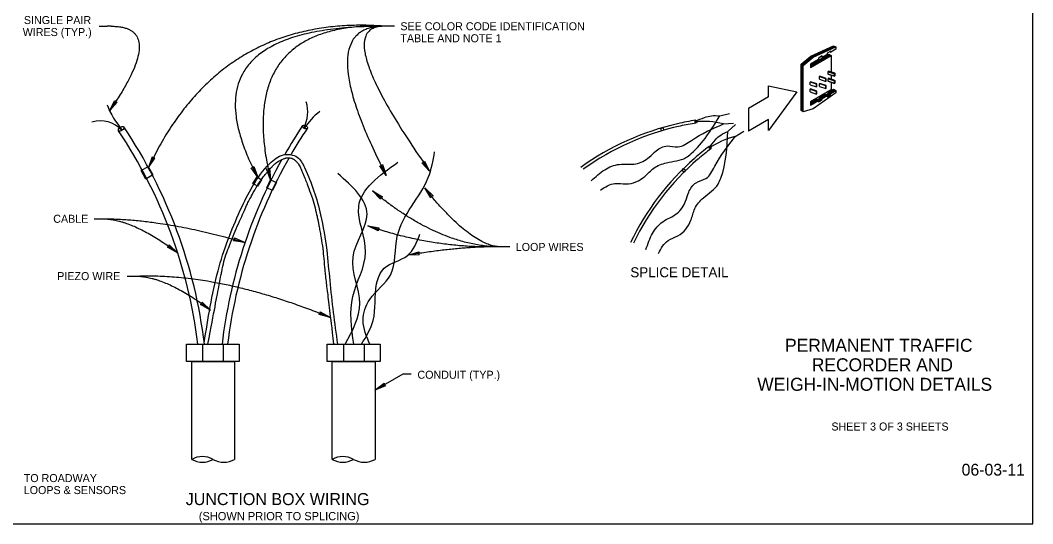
# Model space of a CAD drawing. Extents: x 99862 to 103151, y 100000 to 108076.
# Drawn here: x 101127 to 103151, y 106000 to 107006 of the extents above; entities that cross this region are included whole.
import ezdxf

# ---------------------------------------------------------------- set-up
doc = ezdxf.new("R2010")
doc.units = 0
for name, color, linetype in [('Level 1', 7, 'Continuous'), ('Level 15', 7, 'Continuous'), ('Level 2', 7, 'Continuous'), ('Level 20', 7, 'Continuous'), ('Level 21', 7, 'Continuous'), ('Level 30', 7, 'Continuous'), ('Level 34', 7, 'Continuous'), ('Level 62', 7, 'Continuous')]:
    doc.layers.add(name, color=color, linetype=linetype)

msp = doc.modelspace()

# ---------------------------------------------------------------- linework, layer by layer
at = {"layer": 'Level 1'}
msp.add_lwpolyline([(99862, 105999.5), (103151, 105999.5), (103151, 108075.5), (99862, 108075.5)], close=True, dxfattribs=at)
msp.add_lwpolyline([(99862, 105999.5), (103151, 105999.5), (103151, 108075.5), (99862, 108075.5)], close=True, dxfattribs=at)
at = {"layer": 'Level 15'}
for p, q in [((101285.3, 106994.1), (101301.3, 106994.1)), ((101309.3, 106994.1), (101301.3, 106994.1)), ((101875.2, 106994.1), (101855.5, 106994.1)), ((101275.4, 106609.2), (101291.4, 106609.2)), ((102082.1, 106552.9), (102066.1, 106552.9)), ((102105.8, 106552.9), (102089.8, 106552.9)), ((102105.8, 106552.9), (102103.9, 106552.9)), ((101341.4, 106494.6), (101357.4, 106494.6)), ((101836.3, 106266.4), (101892.5, 106298.9)), ((101892.5, 106298.9), (101908.5, 106298.9))]:
    msp.add_line(p, q, dxfattribs=at)
for points in [[(101306, 106825.2), (101316.4, 106845.7), (101318.2, 106843.1), (101321.3, 106842.3)], [(101383.5, 106711.6), (101396.5, 106730.6), (101393.4, 106731), (101391.2, 106733.3)], [(101945.7, 106704.2), (101930.2, 106721.2), (101933.2, 106722), (101935.1, 106724.6)], [(101602.1, 106692.1), (101589.2, 106711.2), (101592.3, 106711.6), (101594.5, 106713.9)], [(101627.7, 106687.4), (101619.9, 106709), (101623, 106708.6), (101625.7, 106710.3)], [(101858.8, 106695.8), (101845.9, 106714.9), (101849.1, 106715.2), (101851.3, 106717.5)], [(101831.5, 106665.1), (101851.2, 106653.2), (101848.5, 106651.5), (101847.4, 106648.5)], [(101935.9, 106670.9), (101952.7, 106655.1), (101949.7, 106654), (101948.1, 106651.3)], [(101822, 106595.2), (101844.6, 106590.9), (101842.7, 106588.4), (101842.7, 106585.2)], [(101576.7, 106561.7), (101553.9, 106565.1), (101555.7, 106567.7), (101555.5, 106570.8)], [(101442, 106541.3), (101421.7, 106552.2), (101424.3, 106554), (101425.2, 106557.1)], [(101901.9, 106536.5), (101924, 106543.1), (101923.4, 106540), (101924.9, 106537.2)], [(101508, 106426.7), (101487.7, 106437.6), (101490.3, 106439.4), (101491.2, 106442.5)], [(101747.3, 106411.9), (101725, 106417.8), (101727.1, 106420.2), (101727.2, 106423.3)], [(101836.3, 106266.4), (101854.5, 106280.4), (101855.1, 106277.3), (101857.5, 106275.2)]]:
    msp.add_lwpolyline(points, close=True, dxfattribs=at)
for points in [[(101309.3, 106994.1), (101423, 106994.1), (101306, 106825.2)], [(101859.1, 106994.1), (101529, 107019.6), (101384.4, 106712.9)], [(101855.5, 106994.1), (101441.5, 106994.1), (101602.1, 106692.1)], [(101871.5, 106994.1), (101550.7, 107009.3), (101627.7, 106687.4)], [(101855.5, 106994.1), (101705.4, 106994.1), (101858.8, 106695.8)], [(101855.5, 106994.1), (101741.8, 106994.1), (101945.6, 106704.3)], [(102089.8, 106552.9), (101966.3, 106552.9), (101831.5, 106665.1)], [(102089.8, 106552.9), (102029.4, 106552.9), (101935.9, 106670.9)], [(101291.4, 106609.2), (101414.9, 106609.2), (101576.7, 106561.7)], [(101291.4, 106609.2), (101351.8, 106609.2), (101442, 106541.3)], [(102066.1, 106552.9), (101942.6, 106552.9), (101822, 106595.2)], [(102066.1, 106552.9), (102005.8, 106552.9), (101901.9, 106536.5)], [(101357.4, 106494.6), (101527, 106502), (101747.3, 106411.9)], [(101357.4, 106494.6), (101417.8, 106494.6), (101508, 106426.7)]]:
    msp.add_open_spline(points, degree=2, dxfattribs=at)
at = {"layer": 'Level 2'}
for p, q in [((102747.4, 106944.6), (102739.9, 106940.3)), ((102745.3, 106943.4), (102747.4, 106942.2)), ((102757.6, 106948), (102747.4, 106942.2)), ((102747.4, 106942.2), (102747.4, 106944.6)), ((102753, 106955.3), (102757.6, 106952.7)), ((102757.6, 106952.7), (102757.6, 106948)), ((102706.6, 106911.6), (102748.2, 106935.7)), ((102707.6, 106934.6), (102712.1, 106932)), ((102730.2, 106934.7), (102722.7, 106930.3)), ((102722.7, 106930.3), (102722.7, 106927.9)), ((102730.2, 106932.2), (102728, 106933.4)), ((102739.9, 106937.8), (102730.2, 106932.2)), ((102730.2, 106932.2), (102730.2, 106934.7)), ((102739.9, 106940.3), (102739.9, 106937.8)), ((102743.7, 106938.3), (102748.2, 106935.7)), ((102748.2, 106935.7), (102748.2, 106902.7)), ((102692.5, 106915.5), (102688, 106918.1)), ((102742.8, 106904.3), (102742, 106903.5)), ((102742, 106898.3), (102742, 106903.5)), ((102742.8, 106903.3), (102742, 106903.5)), ((102755.4, 106900.1), (102742.8, 106904.3)), ((102754.6, 106899.3), (102742.8, 106903.3)), ((102743, 106904.2), (102755.4, 106900.1)), ((102743, 106903.2), (102754.6, 106899.3)), ((102706.7, 106883.1), (102705.9, 106882.3)), ((102705.9, 106877.1), (102705.9, 106882.3)), ((102706.7, 106882.1), (102705.9, 106882.3)), ((102719.3, 106878.9), (102706.7, 106883.1)), ((102719.3, 106878.9), (102706.7, 106883.1)), ((102718.5, 106878.1), (102706.7, 106882.1)), ((102718.5, 106878.1), (102706.7, 106882.1)), ((102725.7, 106894.2), (102724.9, 106893.4)), ((102724.9, 106888.2), (102724.9, 106893.4)), ((102725.7, 106893.1), (102724.9, 106893.4)), ((102724.9, 106888.2), (102737.5, 106883.9)), ((102738.3, 106889.9), (102725.7, 106894.2)), ((102737.5, 106889.1), (102725.7, 106893.1)), ((102738.3, 106889.9), (102737.5, 106889.1)), ((102737.5, 106883.9), (102737.5, 106889.1)), ((102737.5, 106883.9), (102738.3, 106884.7)), ((102738.3, 106884.7), (102738.3, 106889.9)), ((102742, 106898.3), (102754.6, 106894.1)), ((102742.8, 106890.1), (102742, 106889.3)), ((102742, 106884), (102742, 106889.3)), ((102742.8, 106889), (102742, 106889.3)), ((102742, 106884), (102754.6, 106879.8)), ((102754.6, 106894.1), (102742.2, 106898.2)), ((102754.6, 106879.8), (102742.2, 106884)), ((102755.4, 106885.8), (102742.8, 106890.1)), ((102754.6, 106885), (102742.8, 106889)), ((102743, 106890), (102755.4, 106885.8)), ((102743, 106888.9), (102754.6, 106885)), ((102748.2, 106881.9), (102748.2, 106867.1)), ((102755.4, 106900.1), (102754.6, 106899.3)), ((102755.4, 106900.1), (102754.6, 106899.3)), ((102754.6, 106899.3), (102754.6, 106894.1)), ((102754.6, 106894.1), (102754.6, 106899.3)), ((102754.6, 106894.1), (102755.4, 106894.9)), ((102754.6, 106894.1), (102755.4, 106894.9)), ((102755.4, 106885.8), (102754.6, 106885)), ((102755.4, 106885.8), (102754.6, 106885)), ((102754.6, 106885), (102754.6, 106879.8)), ((102754.6, 106879.8), (102754.6, 106885)), ((102755.4, 106900.1), (102755.4, 106894.9)), ((102755.4, 106894.9), (102755.4, 106900.1)), ((102755.4, 106885.8), (102755.4, 106880.6)), ((102755.4, 106880.6), (102755.4, 106885.8)), ((102623, 106852.9), (102623, 106875)), ((102692.5, 106865.3), (102688, 106867.9)), ((102692.5, 106823.3), (102692.5, 106865.3)), ((102705.9, 106877.1), (102718.5, 106872.9)), ((102705.9, 106877.1), (102718.5, 106872.9)), ((102706.7, 106868.9), (102705.9, 106868.1)), ((102705.9, 106862.8), (102705.9, 106868.1)), ((102706.7, 106867.8), (102705.9, 106868.1)), ((102705.9, 106862.8), (102718.5, 106858.6)), ((102705.9, 106862.8), (102718.5, 106858.6)), ((102748.2, 106867.1), (102706.6, 106843)), ((102719.3, 106864.6), (102706.7, 106868.9)), ((102719.3, 106864.6), (102706.7, 106868.9)), ((102718.5, 106863.8), (102706.7, 106867.8)), ((102718.5, 106863.8), (102706.7, 106867.8)), ((102719.3, 106878.9), (102718.5, 106878.1)), ((102719.3, 106878.9), (102718.5, 106878.1)), ((102718.5, 106872.9), (102718.5, 106878.1)), ((102718.5, 106872.9), (102718.5, 106878.1)), ((102718.5, 106872.9), (102719.3, 106873.7)), ((102718.5, 106872.9), (102719.3, 106873.7)), ((102719.3, 106864.6), (102718.5, 106863.8)), ((102719.3, 106864.6), (102718.5, 106863.8)), ((102718.5, 106858.6), (102718.5, 106863.8)), ((102718.5, 106858.6), (102718.5, 106863.8)), ((102719.3, 106873.7), (102719.3, 106878.9)), ((102719.3, 106873.7), (102719.3, 106878.9)), ((102719.3, 106859.4), (102719.3, 106864.6)), ((102719.3, 106859.4), (102719.3, 106864.6)), ((102725.7, 106879.9), (102724.9, 106879.1)), ((102724.9, 106873.9), (102724.9, 106879.1)), ((102725.7, 106878.8), (102724.9, 106879.1)), ((102724.9, 106873.9), (102737.5, 106869.7)), ((102724.9, 106873.9), (102737.5, 106869.7)), ((102738.3, 106875.7), (102725.7, 106879.9)), ((102738.3, 106875.7), (102725.7, 106879.9)), ((102737.5, 106874.9), (102725.7, 106878.8)), ((102737.5, 106874.9), (102725.7, 106878.8)), ((102738.3, 106875.7), (102737.5, 106874.9)), ((102738.3, 106875.7), (102737.5, 106874.9)), ((102737.5, 106869.7), (102737.5, 106874.9)), ((102737.5, 106869.7), (102737.5, 106874.9)), ((102737.5, 106869.7), (102738.3, 106870.4)), ((102737.5, 106869.7), (102738.3, 106870.4)), ((102738.3, 106870.4), (102738.3, 106875.7)), ((102738.3, 106870.4), (102738.3, 106875.7)), ((102742.9, 106862.6), (102753, 106868.4)), ((102742.9, 106860.1), (102742.9, 106862.6)), ((102742.9, 106862.6), (102747.4, 106860)), ((102745.2, 106861.3), (102755.3, 106867.1)), ((102747.4, 106860), (102757.6, 106865.8)), ((102753, 106868.4), (102757.6, 106865.8)), ((102754.6, 106879.8), (102755.4, 106880.6)), ((102754.6, 106879.8), (102755.4, 106880.6)), ((102757.6, 106865.8), (102757.6, 106861.1)), ((102623, 106852.9), (102583, 106829.9)), ((102757.6, 106861.1), (102712.1, 106829.3)), ((102722.7, 106845.7), (102718.1, 106848.3)), ((102718.5, 106858.6), (102719.3, 106859.4)), ((102718.5, 106858.6), (102719.3, 106859.4)), ((102720.3, 106847), (102725.6, 106850.1)), ((102722.5, 106845.7), (102727.9, 106848.8)), ((102722.7, 106843.2), (102730.2, 106847.5)), ((102722.7, 106845.7), (102722.7, 106843.2)), ((102725.6, 106852.6), (102735.4, 106858.2)), ((102725.6, 106850.1), (102725.6, 106852.6)), ((102725.6, 106852.6), (102730.2, 106850)), ((102730.2, 106847.5), (102725.6, 106850.1)), ((102727.9, 106851.3), (102737.7, 106856.9)), ((102727.9, 106848.8), (102727.9, 106851.3)), ((102730.2, 106850), (102739.9, 106855.6)), ((102730.2, 106847.5), (102730.2, 106850)), ((102735.4, 106858.2), (102739.9, 106855.6)), ((102737.5, 106857), (102742.9, 106860.1)), ((102739.8, 106855.7), (102745.2, 106858.8)), ((102739.9, 106853.2), (102747.4, 106857.5)), ((102739.9, 106855.6), (102739.9, 106853.2)), ((102747.4, 106857.5), (102742.9, 106860.1)), ((102745.2, 106858.8), (102745.2, 106861.3)), ((102747.4, 106857.5), (102747.4, 106860)), ((102583, 106829.9), (102583, 106784.7)), ((102692.5, 106823.3), (102688, 106825.9)), ((102712.1, 106829.3), (102692.5, 106823.3)), ((102623, 106807.8), (102583, 106784.7)), ((102623, 106785.7), (102623, 106807.8))]:
    msp.add_line(p, q, dxfattribs=at)
for points in [[(102688, 106867.9), (102688, 106918.1), (102707.6, 106934.6), (102753, 106955.3)], [(102690.3, 106866.6), (102690.3, 106916.8), (102709.8, 106933.3), (102755.3, 106954)], [(102692.5, 106865.3), (102692.5, 106915.5), (102712.1, 106932), (102757.6, 106952.7)], [(102706.6, 106916.9), (102743.7, 106938.3)], [(102706.6, 106914.2), (102746, 106937)], [(102722.7, 106927.9), (102706.6, 106918.6), (102706.6, 106911.6)], [(102748.2, 106896.4), (102748.2, 106888.3)], [(102623, 106875), (102679.5, 106863), (102623, 106785.7)], [(102688, 106825.9), (102688, 106867.9)], [(102690.3, 106824.6), (102690.3, 106866.6)], [(102706.6, 106841.6), (102718.1, 106848.3)], [(102706.6, 106839), (102720.4, 106847)], [(102706.6, 106843), (102706.6, 106836.4), (102722.7, 106845.7)]]:
    msp.add_lwpolyline(points, dxfattribs=at)
at = {"layer": 'Level 21'}
for p, q in [((102525.4, 106815), (102545.2, 106819.7)), ((102525.4, 106814.8), (102545.2, 106819.6)), ((102532.7, 106799), (102553.1, 106800.2)), ((102532.7, 106798.9), (102553.1, 106800.1)), ((102541.9, 106784), (102557.1, 106797.7)), ((102541.9, 106784), (102557.1, 106797.7)), ((102556, 106773.6), (102573.3, 106784.3)), ((102556, 106773.6), (102573.3, 106784.3))]:
    msp.add_line(p, q, dxfattribs=at)
for points in [[(102411.9, 106791.6), (102413.8, 106786.6), (102409.3, 106784.8), (102407.4, 106789.9)], [(102453.2, 106709.6), (102457.3, 106706.1), (102454.1, 106702.4), (102450, 106705.9)]]:
    msp.add_lwpolyline(points, close=True, dxfattribs=at)
for centre, radius, start, end in [((102561.9, 106267.2), 545.6, 98.8527, 102.8221), ((102493.8, 106648.4), 155.5, 75.503, 96.3909), ((102559.4, 106279.9), 532.6, 102.8706, 125.7956), ((102559.4, 106279.9), 526.9, 102.4053, 125.6163), ((102559.4, 106279.9), 526.9, 98.872, 102.3942), ((102593.4, 106622.7), 155.5, 103.9459, 124.8339), ((102834.8, 106319.9), 545.6, 127.2956, 131.265), ((102825.1, 106326.6), 528.4, 126.8925, 130.4825), ((102826.6, 106330), 532.6, 131.3135, 154.2385), ((102826.6, 106330), 526.9, 130.8483, 154.0592)]:
    msp.add_arc(centre, radius, start, end, dxfattribs=at)
for centre, major_axis in [((102478.1, 106803.4), (-0.82, 2.91)), ((102505.8, 106751.5), (-2.1, 2.17))]:
    msp.add_ellipse(centre, major_axis=major_axis, ratio=0.557118, dxfattribs=at)
for points in [[(102286.9, 106666.5), (102316.1, 106679.8), (102338, 106678.8), (102375.7, 106694), (102393.6, 106710.4), (102419.1, 106721.2), (102457.9, 106731.5), (102468.4, 106739.4), (102525.4, 106814.8)], [(102476.6, 106804), (102495, 106811.7), (102509.2, 106815.2), (102525.4, 106814.8)], [(102268.7, 106685.1), (102295.7, 106707.2), (102324.7, 106718), (102357.6, 106719), (102384.6, 106732.5), (102398.4, 106745.2), (102420.5, 106754.8), (102441.9, 106753), (102468.8, 106766), (102532.7, 106798.9)], [(102402.9, 106540), (102422.2, 106565.6), (102442, 106575.3), (102467.8, 106606.5), (102475.7, 106629.5), (102493.1, 106651.2), (102522.3, 106678.7), (102527.7, 106690.6), (102541.9, 106784)], [(102504.2, 106751.3), (102516.7, 106766.8), (102527.5, 106776.7), (102541.9, 106784)], [(102377.9, 106547.8), (102391.2, 106580), (102411.5, 106603.3), (102440, 106619.9), (102457.3, 106644.7), (102463.4, 106662.3), (102478.3, 106681.3), (102497.9, 106689.9), (102515.5, 106714.2), (102556, 106773.6)]]:
    msp.add_spline(points, degree=3, dxfattribs=at)
at = {"layer": 'Level 30'}
for points in [[(101369, 106705.7), (101383.2, 106713.9), (101392.6, 106696.8), (101378.5, 106688.6)], [(101600.7, 106693), (101609.8, 106687.2), (101601.5, 106674.2), (101592.4, 106680)], [(101627.7, 106687.4), (101639.5, 106681.7), (101631.8, 106665.6), (101620, 106671.3)]]:
    msp.add_lwpolyline(points, close=True, dxfattribs=at)
for centre, radius, start, end in [((100512, 106240.6), 977.5, 6.9349, 33.8459), ((100511.4, 106240.5), 991.2, 6.8428, 33.8815), ((102522.6, 106241.3), 998.7, 146.2911, 150.187), ((102522.6, 106241.3), 987.9, 146.2898, 149.8076), ((102522.6, 106241.3), 998.7, 150.8675, 173.2505), ((102528.1, 106240.2), 993.2, 150.3711, 173.15)]:
    msp.add_arc(centre, radius, start, end, dxfattribs=at)
for centre, major_axis, ratio in [((101329.1, 106789), (-5.11, -3.88), 0.557118), ((101696.4, 106792.6), (-4.86, 2.46), 0.579152)]:
    msp.add_ellipse(centre, major_axis=major_axis, ratio=ratio, dxfattribs=at)
at = {"layer": 'Level 34'}
for p, q in [((102525.4, 106815), (102525.4, 106814.8)), ((101491.9, 106358.6), (101491.9, 106325.3)), ((101533.1, 106358), (101533.1, 106324.7)), ((101773.3, 106358.6), (101773.3, 106325.3)), ((101814.5, 106358), (101814.5, 106324.7))]:
    msp.add_line(p, q, dxfattribs=at)
for points in [[(101459.8, 106358.6), (101565.2, 106358.6), (101565.2, 106324.1), (101459.8, 106324.1)], [(101741.2, 106358.6), (101846.6, 106358.6), (101846.6, 106324.1), (101741.2, 106324.1)]]:
    msp.add_lwpolyline(points, close=True, dxfattribs=at)
for points in [[(101470.3, 106128.2), (101470.3, 106323.9), (101555.9, 106323.9), (101555.9, 106128.2)], [(101751, 106128.2), (101751, 106323.9), (101836.6, 106323.9), (101836.6, 106128.2)]]:
    msp.add_lwpolyline(points, dxfattribs=at)
for centre, radius, start, end in [((101634.1, 106823.1), 68, 331.3678, 16.8859), ((101450.6, 106893.6), 160, 200.6632, 222.0025), ((101802.5, 106723.9), 125.6, 127.5808, 148.4638), ((101287.8, 106746.8), 58.1, 42.2832, 107.0105), ((101491.6, 106091.6), 42.3, 60, 120.1137), ((101772.3, 106091.6), 42.3, 60, 120.1137), ((101491.6, 106164.8), 42.3, 239.9024, 300), ((101534.3, 106165.6), 43.2, 240, 300), ((101772.3, 106164.8), 42.3, 239.9024, 300), ((101815, 106165.6), 43.2, 240, 300)]:
    msp.add_arc(centre, radius, start, end, dxfattribs=at)
for points in [[(101826, 106358.6), (101812.7, 106406), (101826, 106447.9), (101867.2, 106496.8), (101881, 106574.6), (101942.8, 106691.5), (101955.6, 106743.1)], [(101495.2, 106361.2), (101522.9, 106505.4), (101567.2, 106626.1), (101592.4, 106675.1), (101626, 106719.4), (101653.5, 106736.9), (101681, 106732.4), (101695.6, 106711.7), (101727.7, 106617), (101739.9, 106546.7), (101746, 106485.5), (101761.4, 106358.6)], [(101794, 106358.6), (101792.1, 106454.1), (101817.7, 106542.2), (101804, 106633.6), (101882.3, 106722.3)], [(101777.1, 106358.8), (101806, 106439.9), (101792.8, 106533.2), (101820.5, 106618.5), (101762.3, 106699.8)], [(101809.5, 106358.6), (101832.8, 106406), (101839.7, 106479.2), (101854.8, 106510.2), (101901.2, 106535.6), (101926.1, 106578.4)]]:
    msp.add_spline(points, degree=3, dxfattribs=at)
msp.add_open_spline([(101502.6, 106358.6), (101509.1, 106393.8), (101517.3, 106436.3), (101526.2, 106483.1), (101528.7, 106495.9), (101530.3, 106504.4), (101531.1, 106508.5), (101535.8, 106529), (101541.2, 106545), (101553.6, 106576.9), (101560.6, 106592.8), (101571.3, 106616.7), (101574.7, 106624.8), (101581.9, 106640.2), (101585.8, 106647.7), (101593.9, 106662.7), (101598.2, 106670.4), (101607, 106684.5), (101611.7, 106691.1), (101619.5, 106700.9), (101622.3, 106704.1), (101626.6, 106708.9), (101628, 106710.5), (101630.3, 106713), (101631.1, 106713.8), (101632.5, 106715.3), (101633.2, 106716), (101639.7, 106722), (101646.7, 106726), (101654.7, 106729.3), (101655.7, 106729.8), (101657.1, 106730.3), (101657.8, 106730.5), (101660, 106731), (101661.7, 106731.2), (101666.8, 106731.1), (101670.2, 106730.3), (101673.9, 106728.3), (101674.6, 106727.9), (101675.6, 106727.2), (101675.8, 106727), (101676.6, 106726.3), (101677, 106726), (101678.8, 106724.3), (101680.1, 106722.9), (101683.6, 106718.7), (101685.5, 106715.6), (101688, 106710.5), (101688.7, 106708.6), (101690.4, 106704.5), (101692.9, 106698.5), (101695.4, 106692.4), (101700.2, 106680.4), (101703.3, 106672.3), (101711.9, 106648.3), (101716.8, 106632.1), (101721.2, 106611.4), (101722.1, 106607.1), (101723.8, 106598.6), (101724.6, 106594.4), (101727.1, 106581.7), (101728.6, 106573.3), (101732.5, 106548), (101733.9, 106530.9), (101736.3, 106505), (101737.2, 106496.3), (101739.2, 106478.9), (101740.3, 106470.4), (101745.5, 106427.4), (101749.7, 106393), (101753.8, 106358.6)], degree=3, dxfattribs=at)

# ---------------------------------------------------------------- texts
at = {"layer": 'Level 15'}
msp.add_text('06-03-11', height=23.62, dxfattribs=at).set_placement((103008.9, 106095.8))
at = {"layer": 'Level 20'}
for s, height, p in [('SINGLE PAIR', 16, (101134.8, 106998.5)), ('WIRES (TYP.)', 16, (101132.4, 106974.5)), ('SEE COLOR CODE IDENTIFICATION ', 16, (101887.2, 106986.1)), ('TABLE AND NOTE 1', 16, (101887.2, 106962.1)), ('CABLE', 16, (101193.4, 106601.2)), ('LOOP WIRES', 16, (102117.8, 106544.9)), ('PIEZO WIRE', 16, (101201.4, 106486.6)), ('SPLICE DETAIL', 20, (102346.8, 106492.3)), ('CONDUIT (TYP.)', 16, (101921.3, 106289.4)), ('JUNCTION BOX WIRING', 24, (101458.2, 106036.8)), ('(SHOWN PRIOR TO SPLICING)', 16.5, (101484.3, 106006.5))]:
    msp.add_text(s, height=height, dxfattribs=at).set_placement(p)
for s, p in [('TO ROADWAY', (101134.5, 106082.8)), ('LOOPS & SENSORS', (101134.5, 106058.8))]:
    msp.add_text(s, height=16, rotation=360, dxfattribs=at).set_placement(p)
at = {"layer": 'Level 62'}
for s, height, p in [('PERMANENT TRAFFIC', 26, (102656, 106343.3)), ('RECORDER AND ', 26, (102709.5, 106304.3)), ('WEIGH-IN-MOTION DETAILS', 26, (102600.4, 106265.3)), ('SHEET 3 OF 3 SHEETS', 16, (102748.6, 106185.9))]:
    msp.add_text(s, height=height, dxfattribs=at).set_placement(p)

doc.saveas('drawing.dxf')
